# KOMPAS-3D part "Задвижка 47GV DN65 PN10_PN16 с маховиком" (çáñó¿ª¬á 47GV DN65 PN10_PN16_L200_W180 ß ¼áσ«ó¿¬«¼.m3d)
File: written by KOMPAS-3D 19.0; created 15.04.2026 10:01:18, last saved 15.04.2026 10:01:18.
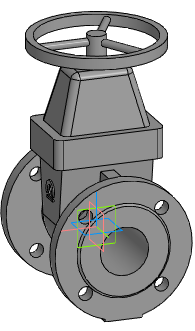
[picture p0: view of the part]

Document properties: Автор: Евгений; Полное имя файла: Z:\3.Личные\kachalov\3d для проектировщиков\2.1 Тип 47GV, 47GV.Z\Задвижка 47GV_DN40-DN600\stp_Задвижка 47GV\Задвижка 47GV DN65 PN10_PN16_L200_W180 с маховиком.m3d

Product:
- Part/product: Задвижка 47GV DN65 PN10_PN16 с маховиком

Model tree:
1. Операция без истории:1  (labels: Задвижка 47GV DN65 PN10_PN16 с маховиком)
